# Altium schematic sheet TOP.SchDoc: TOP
size A4; Author: Silvio Navaretti; CompanyName: Arduino SRL; DrawnBy: Silvio Navaretti; Engineer: Silvio Navaretti; Organization: Arduino SRL; DocumentNumber: ASX00083; SheetNumber: 1; SheetTotal: 11; RevAuthor: Silvio Navaretti
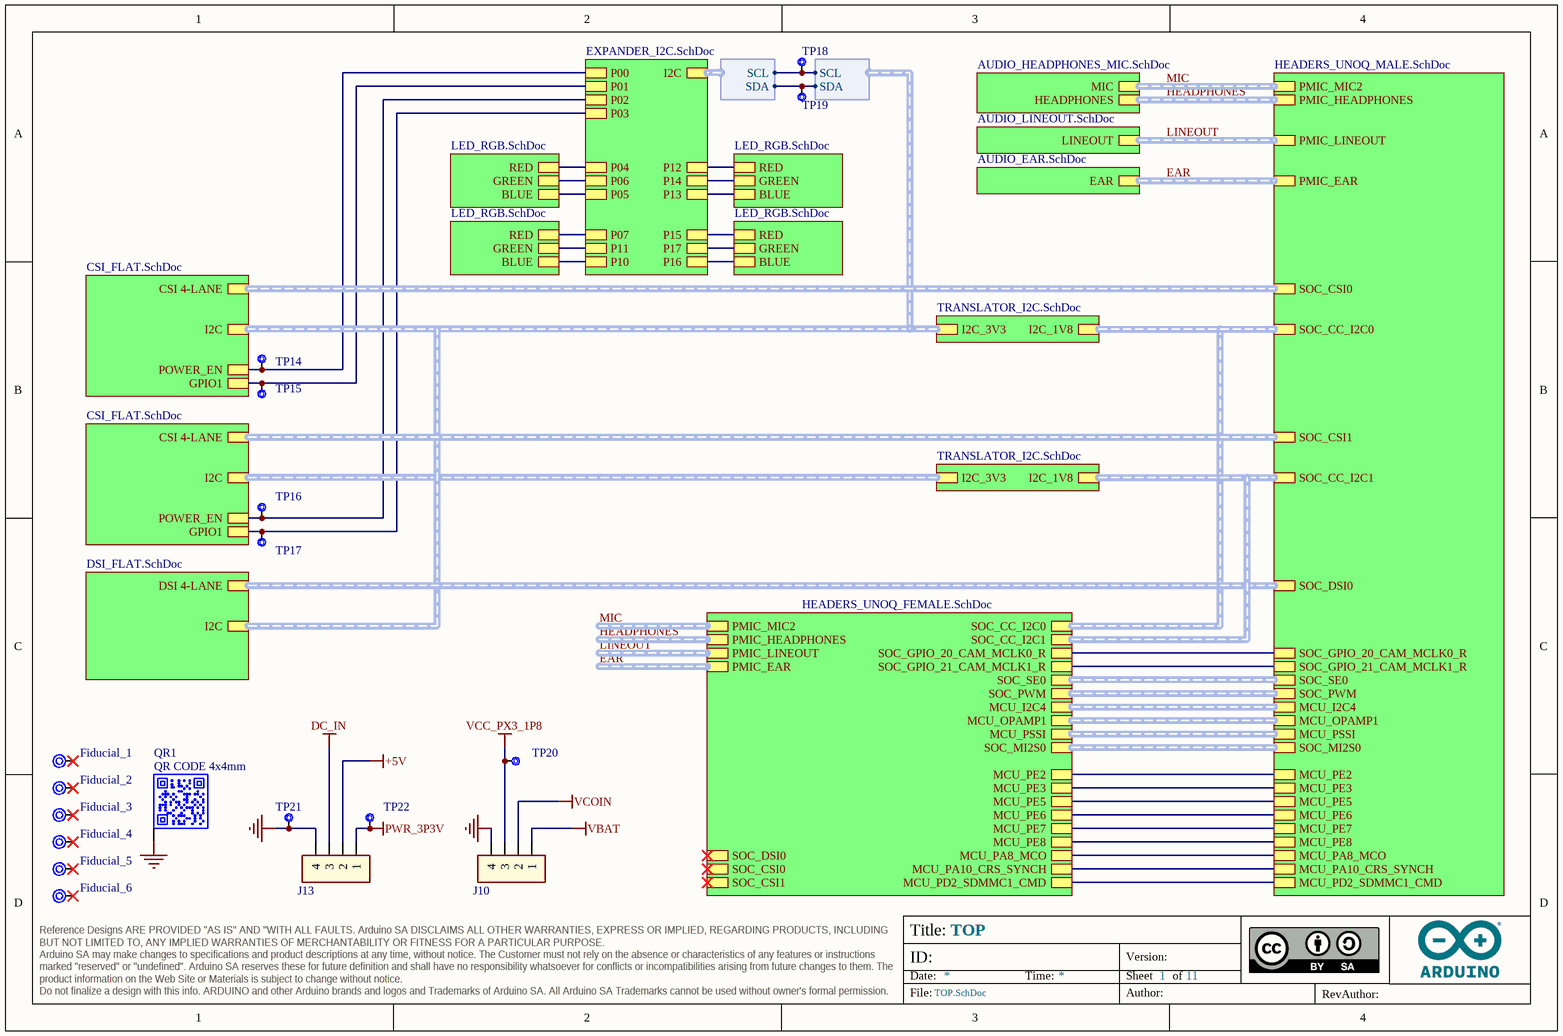
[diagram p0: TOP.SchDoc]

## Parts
Fiducial_1  Fiducial mark 1mm with 2mm solder  [Fiducial mark 1mm with circle-Footprint-1]  (value not drawn)  (no BOM)
Fiducial_2  Fiducial mark 1mm with 2mm solder  [Fiducial mark 1mm with circle-Footprint-1]  (value not drawn)  (no BOM)
Fiducial_3  Fiducial mark 1mm with 2mm solder  [Fiducial mark 1mm with circle-Footprint-1]  (value not drawn)  (no BOM)
Fiducial_4  Fiducial mark 1mm with 2mm solder  [Fiducial mark 1mm with circle-Footprint-1]  (value not drawn)  (no BOM)
Fiducial_5  Fiducial mark 1mm with 2mm solder  [Fiducial mark 1mm with circle-Footprint-1]  (value not drawn)  (no BOM)
Fiducial_6  Fiducial mark 1mm with 2mm solder  [Fiducial mark 1mm with circle-Footprint-1]  (value not drawn)  (no BOM)
J10  HEADER TH 2.54mm VERT. 1x004POS  [PIN HEADER 2.54mm VERT. 1x4POS-Footprint-1]  (value not drawn)  (no BOM)
J13  HEADER TH 2.54mm VERT. 1x004POS  [PIN HEADER 2.54mm VERT. 1x4POS-Footprint-1]  (value not drawn)  (no BOM)
QR1  QR CODE 4x4mm  [QR CODE 4x4mm]  (no BOM)
TP14  Test point 1.00mm  [TP-1.00MM]  (value not drawn)  (no BOM)
TP15  Test point 1.00mm  [TP-1.00MM]  (value not drawn)  (no BOM)
TP16  Test point 1.00mm  [TP-1.00MM]  (value not drawn)  (no BOM)
TP17  Test point 1.00mm  [TP-1.00MM]  (value not drawn)  (no BOM)
TP18  Test point 1.00mm  [TP-1.00MM]  (value not drawn)  (no BOM)
TP19  Test point 1.00mm  [TP-1.00MM]  (value not drawn)  (no BOM)
TP20  Test point 1.00mm  [TP-1.00MM]  (value not drawn)  (no BOM)
TP21  Test point 1.00mm  [TP-1.00MM]  (value not drawn)  (no BOM)
TP22  Test point 1.00mm  [TP-1.00MM]  (value not drawn)  (no BOM)

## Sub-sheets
U_AUDIO_EAR = AUDIO_EAR.SchDoc: EAR (harness EAR)
U_AUDIO_HEADPHONES_MIC = AUDIO_HEADPHONES_MIC.SchDoc: MIC (harness MIC), HEADPHONES (harness HEADPHONES)
U_AUDIO_LINEOUT = AUDIO_LINEOUT.SchDoc: LINEOUT (harness LINEOUT)
U_DSI_FLAT = DSI_FLAT.SchDoc: I2C (harness I2C), DSI 4-LANE (harness SOC_GPIO)
U_FLAT_CSI = CSI_FLAT.SchDoc: I2C (harness I2C), CSI 4-LANE (harness IMOLA_CSI), POWER_EN, GPIO1
U_FLAT_CSI = CSI_FLAT.SchDoc: I2C (harness I2C), CSI 4-LANE (harness IMOLA_CSI), POWER_EN, GPIO1
U_HEADERS_IMOLA_FEMALE = HEADERS_UNOQ_FEMALE.SchDoc: SOC_CSI0 (harness IMOLA_CSI), SOC_GPIO_20_CAM_MCLK0_R, SOC_CC_I2C1 (harness I2C), SOC_CSI1 (harness IMOLA_CSI), SOC_GPIO_21_CAM_MCLK1_R, SOC_CC_I2C0 (harness I2C), SOC_DSI0 (harness IMOLA_DSI), MCU_PSSI (harness PSSI_MCU), PMIC_MIC2 (harness MIC), MCU_PD2_SDMMC1_CMD, MCU_I2C4 (harness I2C), MCU_OPAMP1 (harness MCU_OPAMP), PMIC_LINEOUT (harness LINEOUT), PMIC_HEADPHONES (harness HEADPHONES), SOC_PWM (harness SOC_PWM), SOC_SE0 (harness SOC_GPIO), MCU_PA10_CRS_SYNCH, MCU_PA8_MCO, MCU_PE7, MCU_PE8, PMIC_EAR (harness EAT), SOC_MI2S0 (harness SOC_I2S), MCU_PE2, MCU_PE3, MCU_PE5, MCU_PE6
U_HEADERS_IMOLA_MALE = HEADERS_UNOQ_MALE.SchDoc: SOC_CSI0 (harness IMOLA_CSI), SOC_GPIO_20_CAM_MCLK0_R, SOC_CC_I2C1 (harness I2C), SOC_CSI1 (harness IMOLA_CSI), SOC_GPIO_21_CAM_MCLK1_R, SOC_CC_I2C0 (harness I2C), SOC_DSI0 (harness IMOLA_DSI), MCU_PSSI (harness PSSI_MCU), PMIC_MIC2 (harness MIC), MCU_PD2_SDMMC1_CMD, MCU_I2C4 (harness I2C), MCU_OPAMP1 (harness MCU_OPAMP), PMIC_LINEOUT (harness LINEOUT), PMIC_HEADPHONES (harness HEADPHONES), SOC_PWM (harness SOC_PWM), SOC_SE0 (harness SOC_GPIO), MCU_PA10_CRS_SYNCH, MCU_PA8_MCO, MCU_PE7, MCU_PE8, PMIC_EAR (harness EAT), SOC_MI2S0 (harness SOC_I2S), MCU_PE2, MCU_PE3, MCU_PE5, MCU_PE6
U_LED_RGB_1 = LED_RGB.SchDoc: GREEN, BLUE, RED
U_LED_RGB_2 = LED_RGB.SchDoc: GREEN, BLUE, RED
U_LED_RGB_3 = LED_RGB.SchDoc: GREEN, BLUE, RED
U_LED_RGB_4 = LED_RGB.SchDoc: GREEN, BLUE, RED
U_Sheet1 = EXPANDER_I2C.SchDoc: I2C (harness I2C), P00, P01, P02, P03, P04, P05, P06, P07, P10, P11, P12, P13, P14, P15, P16, P17
U_TRANSLATOR_I2C = TRANSLATOR_I2C.SchDoc: I2C_3V3 (harness I2C), I2C_1V8 (harness I2C)
U_TRANSLATOR_I2C = TRANSLATOR_I2C.SchDoc: I2C_3V3 (harness I2C), I2C_1V8 (harness I2C)

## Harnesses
I2C: SDA, SCL

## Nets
+5V: J13.2
DC_IN: J13.3
GND: J10.4 J13.4 QR1.PAD TP21.X
PWR_3P3V: J13.1 TP22.X
VBAT: J10.1
VCC_PX3_1P8: J10.3 TP20.X
VCOIN: J10.2
NetTP14_X: TP14.X ; sheet U_FLAT_CSI/POWER_EN, sheet U_Sheet1/P00
NetTP15_X: TP15.X ; sheet U_FLAT_CSI/GPIO1, sheet U_Sheet1/P01
NetTP16_X: TP16.X ; sheet U_FLAT_CSI/POWER_EN, sheet U_Sheet1/P02
NetTP17_X: TP17.X ; sheet U_FLAT_CSI/GPIO1, sheet U_Sheet1/P03
NetTP18_X: TP18.X ; sheet U_Sheet1/I2C.SCL, sheet U_FLAT_CSI/I2C.SCL
NetTP19_X: TP19.X ; sheet U_Sheet1/I2C.SDA, sheet U_FLAT_CSI/I2C.SDA
(unnamed): sheet U_HEADERS_IMOLA_MALE/SOC_GPIO_20_CAM_MCLK0_R, sheet U_HEADERS_IMOLA_FEMALE/SOC_GPIO_20_CAM_MCLK0_R
(unnamed): sheet U_HEADERS_IMOLA_MALE/SOC_GPIO_21_CAM_MCLK1_R, sheet U_HEADERS_IMOLA_FEMALE/SOC_GPIO_21_CAM_MCLK1_R  [a separate net that carries the same name]
(unnamed): sheet U_HEADERS_IMOLA_MALE/MCU_PD2_SDMMC1_CMD, sheet U_HEADERS_IMOLA_FEMALE/MCU_PD2_SDMMC1_CMD  [a separate net that carries the same name]
(unnamed): sheet U_HEADERS_IMOLA_MALE/MCU_PA10_CRS_SYNCH, sheet U_HEADERS_IMOLA_FEMALE/MCU_PA10_CRS_SYNCH  [a separate net that carries the same name]
(unnamed): sheet U_HEADERS_IMOLA_MALE/MCU_PA8_MCO, sheet U_HEADERS_IMOLA_FEMALE/MCU_PA8_MCO  [a separate net that carries the same name]
(unnamed): sheet U_HEADERS_IMOLA_MALE/MCU_PE7, sheet U_HEADERS_IMOLA_FEMALE/MCU_PE7  [a separate net that carries the same name]
(unnamed): sheet U_HEADERS_IMOLA_MALE/MCU_PE8, sheet U_HEADERS_IMOLA_FEMALE/MCU_PE8  [a separate net that carries the same name]
(unnamed): sheet U_HEADERS_IMOLA_MALE/MCU_PE2, sheet U_HEADERS_IMOLA_FEMALE/MCU_PE2  [a separate net that carries the same name]
(unnamed): sheet U_HEADERS_IMOLA_MALE/MCU_PE3, sheet U_HEADERS_IMOLA_FEMALE/MCU_PE3  [a separate net that carries the same name]
(unnamed): sheet U_HEADERS_IMOLA_MALE/MCU_PE5, sheet U_HEADERS_IMOLA_FEMALE/MCU_PE5  [a separate net that carries the same name]
(unnamed): sheet U_HEADERS_IMOLA_MALE/MCU_PE6, sheet U_HEADERS_IMOLA_FEMALE/MCU_PE6  [a separate net that carries the same name]
(unnamed): sheet U_Sheet1/P04, sheet U_LED_RGB_1/RED  [a separate net that carries the same name]
(unnamed): sheet U_Sheet1/P05, sheet U_LED_RGB_1/BLUE  [a separate net that carries the same name]
(unnamed): sheet U_Sheet1/P06, sheet U_LED_RGB_1/GREEN  [a separate net that carries the same name]
(unnamed): sheet U_Sheet1/P07, sheet U_LED_RGB_2/RED  [a separate net that carries the same name]
(unnamed): sheet U_Sheet1/P10, sheet U_LED_RGB_2/BLUE  [a separate net that carries the same name]
(unnamed): sheet U_Sheet1/P11, sheet U_LED_RGB_2/GREEN  [a separate net that carries the same name]
(unnamed): sheet U_Sheet1/P12, sheet U_LED_RGB_3/RED  [a separate net that carries the same name]
(unnamed): sheet U_Sheet1/P13, sheet U_LED_RGB_3/BLUE  [a separate net that carries the same name]
(unnamed): sheet U_Sheet1/P14, sheet U_LED_RGB_3/GREEN  [a separate net that carries the same name]
(unnamed): sheet U_Sheet1/P15, sheet U_LED_RGB_4/RED  [a separate net that carries the same name]
(unnamed): sheet U_Sheet1/P16, sheet U_LED_RGB_4/BLUE  [a separate net that carries the same name]
(unnamed): sheet U_Sheet1/P17, sheet U_LED_RGB_4/GREEN  [a separate net that carries the same name]

Not connected (* = marked no-connect by the designer): Fiducial_1 1*; Fiducial_2 1*; Fiducial_3 1*; Fiducial_4 1*; Fiducial_5 1*; Fiducial_6 1*

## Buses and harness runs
harness EAR = sheet U_AUDIO_EAR/EAR = sheet U_HEADERS_IMOLA_MALE/PMIC_EAR
harness EAR = sheet U_HEADERS_IMOLA_FEMALE/PMIC_EAR
harness HEADPHONES = sheet U_AUDIO_HEADPHONES_MIC/HEADPHONES = sheet U_HEADERS_IMOLA_MALE/PMIC_HEADPHONES
harness HEADPHONES = sheet U_HEADERS_IMOLA_FEMALE/PMIC_HEADPHONES
harness LINEOUT = sheet U_AUDIO_LINEOUT/LINEOUT = sheet U_HEADERS_IMOLA_MALE/PMIC_LINEOUT
harness LINEOUT = sheet U_HEADERS_IMOLA_FEMALE/PMIC_LINEOUT
harness MIC = sheet U_AUDIO_HEADPHONES_MIC/MIC = sheet U_HEADERS_IMOLA_MALE/PMIC_MIC2
harness MIC = sheet U_HEADERS_IMOLA_FEMALE/PMIC_MIC2
harness sheet U_DSI_FLAT/DSI 4-LANE = sheet U_HEADERS_IMOLA_MALE/SOC_DSI0
harness sheet U_DSI_FLAT/I2C = sheet U_FLAT_CSI/I2C = sheet U_TRANSLATOR_I2C/I2C_3V3
harness sheet U_FLAT_CSI/CSI 4-LANE = sheet U_HEADERS_IMOLA_MALE/SOC_CSI0
harness sheet U_FLAT_CSI/CSI 4-LANE = sheet U_HEADERS_IMOLA_MALE/SOC_CSI1
harness sheet U_FLAT_CSI/I2C = sheet U_TRANSLATOR_I2C/I2C_3V3
harness sheet U_HEADERS_IMOLA_FEMALE/MCU_I2C4 = sheet U_HEADERS_IMOLA_MALE/MCU_I2C4
harness sheet U_HEADERS_IMOLA_FEMALE/MCU_OPAMP1 = sheet U_HEADERS_IMOLA_MALE/MCU_OPAMP1
harness sheet U_HEADERS_IMOLA_FEMALE/MCU_PSSI = sheet U_HEADERS_IMOLA_MALE/MCU_PSSI
harness sheet U_HEADERS_IMOLA_FEMALE/SOC_CC_I2C0 = sheet U_HEADERS_IMOLA_MALE/SOC_CC_I2C0 = sheet U_TRANSLATOR_I2C/I2C_1V8
harness sheet U_HEADERS_IMOLA_FEMALE/SOC_CC_I2C1 = sheet U_HEADERS_IMOLA_MALE/SOC_CC_I2C1 = sheet U_TRANSLATOR_I2C/I2C_1V8
harness sheet U_HEADERS_IMOLA_FEMALE/SOC_MI2S0 = sheet U_HEADERS_IMOLA_MALE/SOC_MI2S0
harness sheet U_HEADERS_IMOLA_FEMALE/SOC_PWM = sheet U_HEADERS_IMOLA_MALE/SOC_PWM
harness sheet U_HEADERS_IMOLA_FEMALE/SOC_SE0 = sheet U_HEADERS_IMOLA_MALE/SOC_SE0

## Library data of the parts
Fiducial_1-Fiducial_6 = UT0024-A.6
J10 J13 = J0162-A.6: Code Arduino: J0162
QR1 = QR-0001-A.5: QR CODE 4x4mm on layer 34 (This is not a component); Code Arduino: QRCODE_4x4mm
TP14-TP22 = UT0013-A.6: Manufacturer: This is not a component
